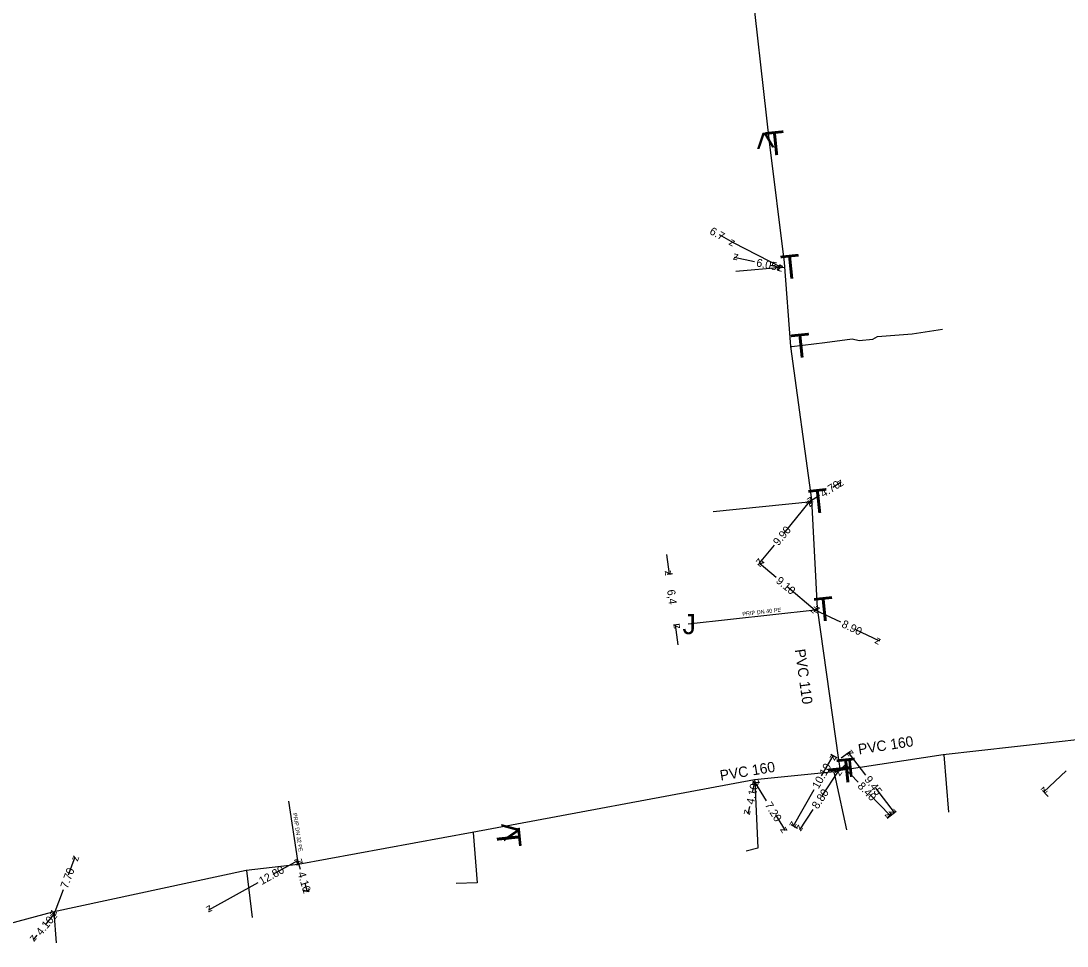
# Model space of a CAD drawing. Extents: x -634006 to -632185, y -1101085 to -1098649.
# Drawn here: x -633420.5 to -633289.8, y -1099143.2 to -1099027.5 of the extents above; entities that cross this region are included whole.
import ezdxf

# ---------------------------------------------------------------- set-up
doc = ezdxf.new("R2010")
doc.units = 0
for name, color, linetype in [('VP Hydrant', 7, 'Continuous'), ('VP Kótování', 7, 'Continuous'), ('VP Popis přípojky', 7, 'Continuous'), ('VP Přípojka', 7, 'Continuous'), ('VP Řad', 7, 'Continuous'), ('VP Řad - popis', 7, 'Continuous'), ('VP Šachta', 7, 'Continuous'), ('VP Šoupě', 7, 'Continuous')]:
    doc.layers.add(name, color=color, linetype=linetype)

msp = doc.modelspace()

# ---------------------------------------------------------------- linework, layer by layer
at = {"layer": 'VP Kótování'}
for points in [[(-633331.45, -1099055.26), (-633333.2, -1099054.28)], [(-633325.44, -1099058.38), (-633331.45, -1099055.26)], [(-633331.31, -1099056.88), (-633331.31, -1099056.88)], [(-633328.81, -1099057.66), (-633331.36, -1099057.12)], [(-633326.86, -1099058.08), (-633325.44, -1099058.38)], [(-633325.39, -1099058.13), (-633325.39, -1099058.13)], [(-633319.03, -1099085.81), (-633317.99, -1099085.15)], [(-633317.86, -1099085.36), (-633317.86, -1099085.36)], [(-633320.69, -1099086.87), (-633321.96, -1099087.67)], [(-633325.14, -1099091.55), (-633321.96, -1099087.67)], [(-633321.82, -1099087.88), (-633321.82, -1099087.88)], [(-633321.76, -1099087.83), (-633321.76, -1099087.83)], [(-633326.39, -1099093.08), (-633328.23, -1099095.33)], [(-633339.81, -1099094.22), (-633339.49, -1099096.7)], [(-633328.42, -1099095.17), (-633328.42, -1099095.17)], [(-633326.1, -1099097.11), (-633328.23, -1099095.33)], [(-633328.07, -1099095.14), (-633328.07, -1099095.14)], [(-633339.06, -1099096.64), (-633339.74, -1099096.73)], [(-633324.8, -1099098.19), (-633321.25, -1099101.17)], [(-633318.05, -1099102.7), (-633321.25, -1099101.17)], [(-633321.14, -1099100.94), (-633321.14, -1099100.94)], [(-633321.09, -1099100.97), (-633321.09, -1099100.97)], [(-633338.24, -1099102.99), (-633338.93, -1099103.08)], [(-633338.37, -1099105.52), (-633338.68, -1099103.04)], [(-633316.28, -1099103.56), (-633313.23, -1099105.03)], [(-633313.12, -1099104.8), (-633313.12, -1099104.8)], [(-633320.44, -1099121.89), (-633319.02, -1099119.39)], [(-633318.48, -1099119.7), (-633319.28, -1099119.24)], [(-633317.98, -1099119.66), (-633316.85, -1099118.8)], [(-633314.93, -1099121.82), (-633317.09, -1099118.99)], [(-633318.1, -1099121.1), (-633317.52, -1099120.54)], [(-633315.87, -1099122.68), (-633317.74, -1099120.75)], [(-633320.37, -1099124.38), (-633318.32, -1099121.31)], [(-633318.62, -1099121.31), (-633318.62, -1099121.31)], [(-633289.89, -1099121.27), (-633292.68, -1099123.91)], [(-633329.09, -1099122.64), (-633329.09, -1099122.64)], [(-633329.09, -1099123.98), (-633328.8, -1099122.64)], [(-633327.31, -1099125.02), (-633328.8, -1099122.64)], [(-633328.49, -1099122.64), (-633328.49, -1099122.64)], [(-633313.7, -1099123.44), (-633311.36, -1099126.5)], [(-633321.42, -1099123.63), (-633324, -1099128.18)], [(-633314.44, -1099124.17), (-633311.91, -1099126.8)], [(-633292.12, -1099124.5), (-633292.85, -1099123.73)], [(-633329.47, -1099125.72), (-633329.67, -1099126.65)], [(-633321.52, -1099126.1), (-633323.2, -1099128.63)], [(-633329.37, -1099126.65), (-633329.37, -1099126.65)], [(-633326.21, -1099126.77), (-633324.98, -1099128.75)], [(-633312.27, -1099127.15), (-633311.69, -1099126.59)], [(-633312.25, -1099127.18), (-633311.13, -1099126.32)], [(-633324.68, -1099128.75), (-633324.68, -1099128.75)], [(-633323.46, -1099128.48), (-633324.26, -1099128.03)], [(-633322.9, -1099128.63), (-633322.9, -1099128.63)], [(-633414.52, -1099134.28), (-633413.69, -1099132.02)], [(-633413.46, -1099132.11), (-633413.46, -1099132.11)], [(-633388.94, -1099134.19), (-633385.86, -1099132.48)], [(-633386.16, -1099132.48), (-633386.16, -1099132.48)], [(-633385.53, -1099133.61), (-633385.86, -1099132.48)], [(-633385.56, -1099132.48), (-633385.56, -1099132.48)], [(-633390.89, -1099135.28), (-633397.05, -1099138.7)], [(-633385.02, -1099135.33), (-633384.7, -1099136.41)], [(-633415.21, -1099136.13), (-633416.35, -1099139.24)], [(-633384.4, -1099136.41), (-633384.4, -1099136.41)], [(-633417.41, -1099140.52), (-633416.35, -1099139.24)], [(-633396.75, -1099138.7), (-633396.75, -1099138.7)], [(-633416.16, -1099139.4), (-633416.16, -1099139.4)], [(-633416.12, -1099139.33), (-633416.12, -1099139.33)], [(-633418.48, -1099141.82), (-633418.96, -1099142.41)], [(-633418.77, -1099142.57), (-633418.77, -1099142.57)]]:
    msp.add_lwpolyline(points, dxfattribs=at)
at = {"layer": 'VP Přípojka'}
for points in [[(-633325.44, -1099058.38), (-633331.16, -1099058.88)], [(-633325.44, -1099058.38), (-633325.03, -1099058.32)], [(-633324.27, -1099068.25), (-633324.15, -1099068.24), (-633320.05, -1099067.74), (-633316.62, -1099067.28), (-633315.74, -1099067.49), (-633314.05, -1099067.32), (-633313.46, -1099066.97), (-633309.15, -1099066.67), (-633305.32, -1099066.07)], [(-633321.65, -1099087.64), (-633334.01, -1099088.92)], [(-633320.94, -1099100.96), (-633321.25, -1099101.17), (-633337.11, -1099102.94)], [(-633305.17, -1099119.26), (-633304.58, -1099126.44)], [(-633318.91, -1099121.42), (-633318.71, -1099122.33), (-633317.32, -1099128.63)], [(-633328.81, -1099122.39), (-633328.8, -1099122.64), (-633328.39, -1099130.95), (-633329.87, -1099131.32)], [(-633385.88, -1099132.99), (-633385.86, -1099132.48), (-633387.01, -1099125.05)], [(-633363.99, -1099128.97), (-633363.46, -1099135.26), (-633366.09, -1099135.37)], [(-633392.3, -1099133.74), (-633391.57, -1099139.61)], [(-633416.38, -1099138.93), (-633416.07, -1099142.76)]]:
    msp.add_lwpolyline(points, dxfattribs=at)
at = {"layer": 'VP Řad'}
for points in [[(-633318.07, -1099121.22), (-633318.29, -1099119.91), (-633320.94, -1099100.96), (-633321.66, -1099087.4), (-633324.27, -1099068.25), (-633325.08, -1099057.75), (-633326.94, -1099042.67), (-633329.48, -1099020.01)], [(-633282.97, -1099116.77), (-633305.25, -1099119.27), (-633318.07, -1099121.22)], [(-633318.07, -1099121.22), (-633318.43, -1099121.34), (-633328.81, -1099122.39), (-633364.12, -1099128.99), (-633385.83, -1099132.98), (-633392.32, -1099133.74), (-633416.51, -1099138.95), (-633432.36, -1099143.18)]]:
    msp.add_lwpolyline(points, dxfattribs=at)

# ---------------------------------------------------------------- texts
at = {"layer": 'VP Hydrant'}
for rotation, p in [(95.8635, (-633325.97, -1099043.5)), (9.5529, (-633360.25, -1099130.45))]:
    msp.add_text('>', height=3, rotation=rotation, dxfattribs=at).set_placement(p)
at = {"layer": 'VP Kótování'}
for s, rotation, p in [('6.7', 330.7731, (-633334.54, -1099054.11)), ('z', 330.7731, (-633332.13, -1099055.45)), ('z', 167.9992, (-633330.77, -1099056.73)), ('6.05', 347.9992, (-633328.67, -1099058.2)), ('z', 332.5718, (-633326.12, -1099058.59)), ('z', 347.9992, (-633326.04, -1099058.76)), ('4.70', 32.4422, (-633320.21, -1099087.15)), ('z', 32.4422, (-633318.14, -1099085.84)), ('z', 50.6768, (-633321.89, -1099088.37)), ('z', 212.4422, (-633321.8, -1099086.98)), ('9.90', 50.6768, (-633325.84, -1099093.21)), ('z', 230.6768, (-633328.3, -1099094.63)), ('z', 140.1219, (-633327.53, -1099095.27)), ('z', 277.2918, (-633340.05, -1099096.27)), ('9.10', 320.1219, (-633326.23, -1099097.66)), ('6,4', 277.2918, (-633339.75, -1099098.68)), ('z', 320.1219, (-633321.95, -1099101.23)), ('z', 154.2585, (-633320.58, -1099100.93)), ('8.90', 334.2585, (-633318.04, -1099103.26)), ('z', 97.2918, (-633338.12, -1099103.48)), ('z', 334.2584, (-633313.9, -1099105.26)), ('z', 60.4451, (-633318.83, -1099120.07)), ('z', 127.3113, (-633316.39, -1099119.08)), ('10.10', 60.4451, (-633320.84, -1099123.61)), ('z', 133.9147, (-633317.03, -1099120.76)), ('z', 56.2919, (-633318.18, -1099122)), ('9.45', 307.3113, (-633315.15, -1099122.37)), ('4.10', 77.6818, (-633328.91, -1099125.54)), ('z', 77.6818, (-633328.41, -1099123.24)), ('z', 121.9927, (-633328.11, -1099122.8)), ('8.80', 56.2919, (-633320.93, -1099126.13)), ('8.40', 313.9147, (-633316.03, -1099123.25)), ('z', 223.5183, (-633292.66, -1099123.21)), ('z', 257.6818, (-633330.05, -1099126.05)), ('7.20', 301.9927, (-633327.58, -1099125.54)), ('z', 307.3113, (-633312.07, -1099126.41)), ('z', 313.9147, (-633312.62, -1099126.79)), ('z', 301.9927, (-633325.67, -1099128.59)), ('z', 240.4451, (-633324.19, -1099127.5)), ('z', 236.2919, (-633323.34, -1099127.94)), ('z', 69.7575, (-633413.39, -1099132.66)), ('z', 29.082, (-633386.06, -1099133.16)), ('z', 106.477, (-633385.24, -1099132.82)), ('7.70', 69.7575, (-633414.65, -1099136.07)), ('12.80', 29.082, (-633390.39, -1099135.57)), ('4.10', 286.4771, (-633385.92, -1099134.04)), ('z', 286.4771, (-633385.32, -1099136.07)), ('z', 249.7575, (-633416.65, -1099138.6)), ('z', 50.5415, (-633416.29, -1099139.95)), ('z', 209.082, (-633396.86, -1099138.02)), ('4.10', 50.5415, (-633417.93, -1099141.95)), ('z', 230.5415, (-633419.03, -1099141.71))]:
    msp.add_text(s, height=1, rotation=rotation, dxfattribs=at).set_placement(p)
at = {"layer": 'VP Popis přípojky'}
for s, rotation, p in [('PRIP DN 40 PE', 6.3775, (-633330.32, -1099101.92)), ('PRIP DN 32 PE', 278.7415, (-633386.49, -1099126.59))]:
    msp.add_text(s, height=0.5, rotation=rotation, dxfattribs=at).set_placement(p)
at = {"layer": 'VP Řad - popis'}
for s, rotation, p in [('PVC 110', 277.9535, (-633323.79, -1099106.13)), ('PVC 160', 8.68, (-633315.78, -1099119.23)), ('PVC 160', 9.3868, (-633333.04, -1099122.51))]:
    msp.add_text(s, height=1.3, rotation=rotation, dxfattribs=at).set_placement(p)
at = {"layer": 'VP Šachta'}
msp.add_text('J', height=2.5, dxfattribs=at).set_placement((-633337.82, -1099104.19))
at = {"layer": 'VP Šoupě'}
for rotation, p in [(5.8635, (-633327.27, -1099044.44)), (5.8635, (-633325.38, -1099059.88)), (5.8635, (-633324.09, -1099069.74)), (6.236, (-633321.89, -1099089.17)), (5.8635, (-633321.19, -1099102.67)), (5.8635, (-633318.37, -1099122.84)), (275.8635, (-633319.79, -1099119.97)), (275.8635, (-633361.14, -1099128.6))]:
    msp.add_text('T', height=3, rotation=rotation, dxfattribs=at).set_placement(p)

doc.saveas('drawing.dxf')
